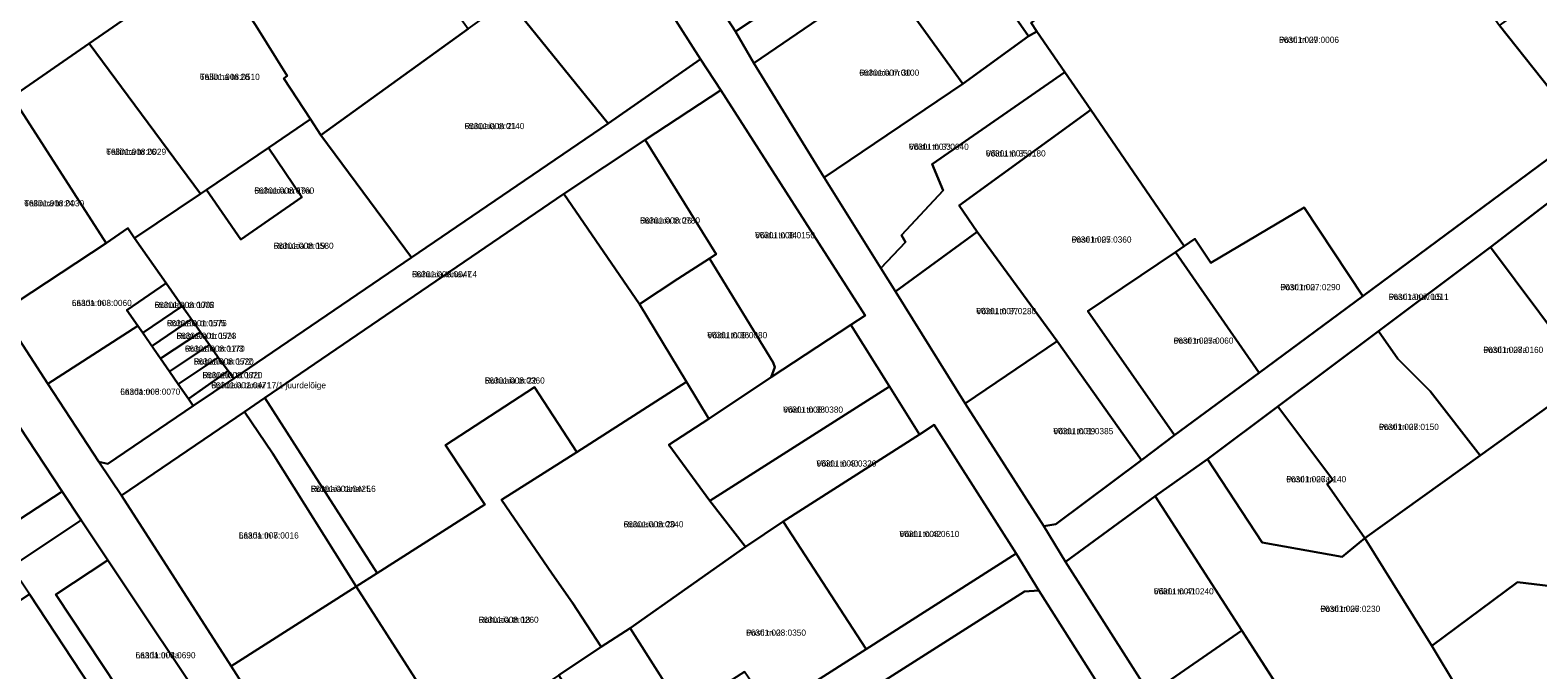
# Model space of a CAD drawing. Extents: x 632278 to 636344, y 6578401 to 6583362.
# Drawn here: x 634219.9 to 634584.8, y 6581569.1 to 6581724.1 of the extents above; entities that cross this region are included whole.
import ezdxf

# ---------------------------------------------------------------- set-up
doc = ezdxf.new("R2010")
doc.units = 0
for name, color, linetype in [('L_AADRESS', 7, 'Continuous'), ('PIIR', 7, 'Continuous'), ('TUNNUS', 7, 'Continuous')]:
    doc.layers.add(name, color=color, linetype=linetype)

msp = doc.modelspace()

# ---------------------------------------------------------------- linework, layer by layer
at = {"layer": 'PIIR'}
for points in [[(634390.59, 6581723.7), (634406.97, 6581734.67), (634430.14, 6581750.99), (634463.52, 6581774.56), (634480.53, 6581786.77), (634533.21, 6581825.04), (634540.52, 6581819.75), (634516.54, 6581802.4), (634487.79, 6581781.63), (634480.74, 6581776.54), (634463.1, 6581763.8), (634442.96, 6581749.29), (634426.52, 6581737.65), (634395.02, 6581716.06)], [(634542.38, 6581659.66), (634528.25, 6581681.09), (634505.64, 6581667.69), (634501.78, 6581673.52), (634499.19, 6581671.71), (634476.56, 6581704.76), (634470.29, 6581713.85), (634463.54, 6581723.76), (634462.17, 6581725.81), (634478.91, 6581739.1), (634495.28, 6581752.06), (634495.31, 6581755.28), (634480.74, 6581776.54), (634487.79, 6581781.63), (634501.69, 6581761.6), (634506.42, 6581760.84), (634533.2, 6581780.82), (634535.35, 6581782.3), (634539.41, 6581777.64), (634559.86, 6581753.58), (634578.17, 6581731.87), (634573.15, 6581728.47), (634575.51, 6581725.17), (634596.02, 6581699.37)], [(634384.46, 6581770.81), (634385.8, 6581770.55), (634390.5, 6581773.35), (634392.48, 6581770.44), (634390.31, 6581758.54), (634406.97, 6581734.67), (634390.59, 6581723.7), (634366.06, 6581761.71)], [(634287.77, 6581702.49), (634281.27, 6581712.39), (634282.11, 6581712.99), (634274.53, 6581725.21), (634263.89, 6581741.44), (634297.55, 6581763.99), (634325.89, 6581724.38), (634290.29, 6581698.63)], [(634463.54, 6581723.76), (634461.5, 6581722.59), (634442.96, 6581749.29), (634463.1, 6581763.8), (634478.91, 6581739.1), (634462.17, 6581725.81)], [(634332.09, 6581728.85), (634329.74, 6581732.36), (634338.88, 6581738.71), (634359, 6581752.83), (634371.92, 6581733.15), (634382.16, 6581717.03), (634359.75, 6581701.47), (634335.78, 6581731.17)], [(634426.52, 6581737.65), (634442.96, 6581749.29), (634461.5, 6581722.59), (634445.61, 6581711.1)], [(634575.51, 6581725.17), (634601.75, 6581744.08), (634619.36, 6581722.13), (634619.15, 6581716.25), (634596.02, 6581699.37)], [(634234.17, 6581720.87), (634263.89, 6581741.44), (634274.53, 6581725.21), (634282.11, 6581712.99), (634281.27, 6581712.39), (634287.77, 6581702.49), (634277.55, 6581695.55), (634262.59, 6581685.41), (634261.09, 6581684.41)], [(634395.02, 6581716.06), (634426.52, 6581737.65), (634445.61, 6581711.1), (634412.03, 6581688.4)], [(634290.29, 6581698.63), (634325.89, 6581724.38), (634332.09, 6581728.85), (634335.78, 6581731.17), (634359.75, 6581701.47), (634312.2, 6581669.01)], [(634412.03, 6581688.4), (634445.61, 6581711.1), (634461.5, 6581722.59), (634463.54, 6581723.76), (634470.29, 6581713.85), (634438.2, 6581691.62), (634440.85, 6581685.2), (634430.79, 6581674.37), (634431.73, 6581672.7), (634425.76, 6581666.4)], [(634465.25, 6581603.88), (634468.13, 6581604.4), (634488.84, 6581619.91), (634496.87, 6581625.93), (634517.35, 6581641.08), (634542.38, 6581659.66), (634596.02, 6581699.37), (634619.15, 6581716.25), (634619.36, 6581722.13), (634629.3, 6581709.96), (634624.28, 6581710.25), (634591.07, 6581685.14), (634573.32, 6581671.48), (634546.18, 6581651.15), (634521.83, 6581632.88), (634504.86, 6581620.14), (634492.15, 6581611.16), (634470.5, 6581595.28)], [(634234.17, 6581720.87), (634261.09, 6581684.41), (634245.18, 6581673.71), (634243.53, 6581676.07), (634238.31, 6581672.46), (634215.55, 6581707.95)], [(634238.7, 6581619.03), (634259.34, 6581633.1), (634269.19, 6581639.69), (634312.2, 6581669.01), (634359.75, 6581701.47), (634382.16, 6581717.03), (634387.02, 6581709.56), (634368.71, 6581697.52), (634349.07, 6581684.39), (634276.71, 6581634.98), (634271.75, 6581631.6), (634241.99, 6581611.37), (634236.5, 6581619.47)], [(634449.07, 6581675.23), (634429.3, 6581660.73), (634425.76, 6581666.4), (634431.73, 6581672.7), (634430.79, 6581674.37), (634440.85, 6581685.2), (634438.2, 6581691.62), (634470.29, 6581713.85), (634476.56, 6581704.76), (634444.69, 6581681.63)], [(634213, 6581655.75), (634200.62, 6581674.99), (634198.64, 6581684.01), (634200.14, 6581693.09), (634205.31, 6581700.81), (634215.55, 6581707.95), (634238.31, 6581672.46)], [(634385.92, 6581669.79), (634368.71, 6581697.52), (634387.02, 6581709.56), (634421.96, 6581654.97), (634418.54, 6581652.72), (634399.27, 6581640), (634400.16, 6581642.46), (634399.72, 6581643.55), (634384.33, 6581668.75)], [(634449.07, 6581675.23), (634444.69, 6581681.63), (634476.56, 6581704.76), (634499.19, 6581671.71), (634497.12, 6581670.26), (634475.86, 6581655.98), (634496.87, 6581625.93), (634488.84, 6581619.91), (634468.44, 6581648.74)], [(634277.55, 6581695.55), (634287.77, 6581702.49), (634290.29, 6581698.63), (634312.2, 6581669.01), (634269.19, 6581639.69), (634267.81, 6581641.52), (634265.41, 6581644.76), (634263.27, 6581647.84), (634261.09, 6581650.95), (634256.71, 6581657.23), (634252.82, 6581662.79), (634245.18, 6581673.71), (634261.09, 6581684.41), (634262.59, 6581685.41), (634270.9, 6581673.36), (634285.64, 6581683.59)], [(634262.59, 6581685.41), (634277.55, 6581695.55), (634285.64, 6581683.59), (634270.9, 6581673.36)], [(634368.71, 6581697.52), (634385.92, 6581669.79), (634384.33, 6581668.75), (634376.63, 6581663.86), (634367.4, 6581657.66), (634349.07, 6581684.39)], [(634591.07, 6581685.14), (634616.16, 6581653.62), (634596.98, 6581639.85), (634573.32, 6581671.48)], [(634178.6, 6581682.42), (634181.78, 6581682), (634227.65, 6581612.34), (634201.03, 6581594.97), (634184.81, 6581620.64), (634154.84, 6581666.74)], [(634329.95, 6581609.13), (634303.87, 6581592.51), (634276.71, 6581634.98), (634349.07, 6581684.39), (634367.4, 6581657.66), (634378.72, 6581638.87), (634352.19, 6581621.81), (634341.95, 6581637.56), (634320.42, 6581623.52)], [(634497.12, 6581670.26), (634499.19, 6581671.71), (634501.78, 6581673.52), (634505.64, 6581667.69), (634528.25, 6581681.09), (634542.38, 6581659.66), (634517.35, 6581641.08)], [(634213, 6581655.75), (634238.31, 6581672.46), (634243.53, 6581676.07), (634245.18, 6581673.71), (634252.82, 6581662.79), (634243.3, 6581656.27), (634245.94, 6581652.46), (634224.2, 6581638.41)], [(634429.3, 6581660.73), (634449.07, 6581675.23), (634468.44, 6581648.74), (634446.2, 6581633.64)], [(634517.35, 6581641.08), (634496.87, 6581625.93), (634475.86, 6581655.98), (634497.12, 6581670.26)], [(634558.68, 6581636.62), (634550.9, 6581644.45), (634546.18, 6581651.15), (634573.32, 6581671.48), (634596.98, 6581639.85), (634570.79, 6581621.02)], [(634376.63, 6581663.86), (634384.33, 6581668.75), (634399.72, 6581643.55), (634400.16, 6581642.46), (634399.27, 6581640), (634384.14, 6581629.88), (634378.72, 6581638.87), (634367.4, 6581657.66)], [(634243.3, 6581656.27), (634252.82, 6581662.79), (634256.71, 6581657.23), (634247.14, 6581650.73), (634245.94, 6581652.46)], [(634256.71, 6581657.23), (634258.93, 6581654.05), (634249.39, 6581647.48), (634247.14, 6581650.73)], [(634236.5, 6581619.47), (634224.2, 6581638.41), (634245.94, 6581652.46), (634247.14, 6581650.73), (634251.44, 6581644.52), (634253.6, 6581641.4), (634255.73, 6581638.31), (634258.19, 6581634.76), (634259.34, 6581633.1), (634238.7, 6581619.03)], [(634261.09, 6581650.95), (634251.44, 6581644.52), (634249.39, 6581647.48), (634258.93, 6581654.05)], [(634374.47, 6581623.59), (634384.14, 6581629.88), (634399.27, 6581640), (634418.54, 6581652.72), (634427.83, 6581637.77), (634384.4, 6581610.07)], [(634559.13, 6581574.95), (634542.92, 6581601.03), (634570.79, 6581621.02), (634596.98, 6581639.85), (634616.16, 6581653.62), (634622.65, 6581644.36), (634632.64, 6581630.11), (634606.62, 6581611.45), (634614.1, 6581600.53), (634608.38, 6581596.32), (634597.33, 6581588.27), (634579.85, 6581590.37)], [(634251.44, 6581644.52), (634261.09, 6581650.95), (634263.27, 6581647.84), (634253.6, 6581641.4)], [(634446.2, 6581633.64), (634468.44, 6581648.74), (634488.84, 6581619.91), (634468.13, 6581604.4), (634465.25, 6581603.88)], [(634533.76, 6581614.08), (634535.12, 6581615.13), (634521.83, 6581632.88), (634546.18, 6581651.15), (634550.9, 6581644.45), (634558.68, 6581636.62), (634570.79, 6581621.02), (634542.92, 6581601.03)], [(634253.6, 6581641.4), (634263.27, 6581647.84), (634265.41, 6581644.76), (634255.73, 6581638.31)], [(634255.73, 6581638.31), (634265.41, 6581644.76), (634267.81, 6581641.52), (634258.19, 6581634.76)], [(634269.19, 6581639.69), (634259.34, 6581633.1), (634258.19, 6581634.76), (634267.81, 6581641.52)], [(634298.81, 6581589.28), (634303.87, 6581592.51), (634329.95, 6581609.13), (634320.42, 6581623.52), (634341.95, 6581637.56), (634352.19, 6581621.81), (634333.97, 6581610.3), (634346.21, 6581592.35), (634351.19, 6581585.34), (634358.09, 6581574.66), (634347.82, 6581567.79), (634331.08, 6581556.63), (634331.92, 6581555.12), (634324.08, 6581549.93)], [(634358.09, 6581574.66), (634351.19, 6581585.34), (634346.21, 6581592.35), (634333.97, 6581610.3), (634352.19, 6581621.81), (634378.72, 6581638.87), (634384.14, 6581629.88), (634374.47, 6581623.59), (634384.4, 6581610.07), (634393.05, 6581598.93), (634365.1, 6581579.21)], [(634384.4, 6581610.07), (634427.83, 6581637.77), (634435.17, 6581626.1), (634402.11, 6581605.04), (634393.05, 6581598.93)], [(634276.71, 6581634.98), (634303.87, 6581592.51), (634298.81, 6581589.28), (634278.53, 6581621.61), (634271.75, 6581631.6)], [(634271.75, 6581631.6), (634278.53, 6581621.61), (634298.81, 6581589.28), (634268.56, 6581570.01), (634241.99, 6581611.37)], [(634537.45, 6581596.52), (634518.08, 6581599.98), (634504.86, 6581620.14), (634521.83, 6581632.88), (634535.12, 6581615.13), (634533.76, 6581614.08), (634542.92, 6581601.03)], [(634402.11, 6581605.04), (634435.17, 6581626.1), (634438.67, 6581628.47), (634458.52, 6581597.29), (634422.2, 6581574.09)], [(634526.88, 6581557.26), (634513.13, 6581578.68), (634492.15, 6581611.16), (634504.86, 6581620.14), (634518.08, 6581599.98), (634537.45, 6581596.52), (634542.92, 6581601.03), (634559.13, 6581574.95), (634565.3, 6581564.63), (634538.81, 6581546.18), (634536.83, 6581548.73), (634529.38, 6581553.31)], [(634122.7, 6581544.91), (634155.45, 6581566.31), (634155.98, 6581565.48), (634173.91, 6581577.27), (634196.07, 6581591.73), (634201.03, 6581594.97), (634227.65, 6581612.34), (634232.23, 6581605.4), (634215.35, 6581594.07), (634143.16, 6581546.1), (634126.02, 6581534.77)], [(634470.5, 6581595.28), (634492.15, 6581611.16), (634513.13, 6581578.68), (634490.9, 6581563.22)], [(634215.35, 6581594.07), (634232.23, 6581605.4), (634238.73, 6581595.7), (634226.13, 6581587.37), (634252.18, 6581547.97), (634258.61, 6581538.24), (634265.76, 6581527.41), (634283.88, 6581498.21), (634285.44, 6581499.17), (634288.97, 6581494.15), (634283.51, 6581490.57), (634253.15, 6581536.68), (634219.73, 6581587.47)], [(634385.83, 6581564.23), (634389.39, 6581559.07), (634392.04, 6581554.92), (634383.79, 6581549.73), (634365.1, 6581579.21), (634393.05, 6581598.93), (634402.11, 6581605.04), (634422.2, 6581574.09), (634398.79, 6581559.22), (634396.33, 6581563.46), (634392.79, 6581568.66)], [(634311.42, 6581503.24), (634349.58, 6581527.87), (634366.58, 6581538.6), (634383.79, 6581549.73), (634392.04, 6581554.92), (634398.79, 6581559.22), (634422.2, 6581574.09), (634458.52, 6581597.29), (634464.03, 6581588.35), (634460.52, 6581588.08), (634423.26, 6581564.33), (634392.45, 6581544.4), (634388.55, 6581541.72), (634370.84, 6581530.29), (634352.1, 6581517.99), (634334.35, 6581506.61), (634316.67, 6581495.15)], [(634238.73, 6581595.7), (634264.73, 6581556.64), (634252.18, 6581547.97), (634226.13, 6581587.37)], [(634538.81, 6581546.18), (634565.3, 6581564.63), (634559.13, 6581574.95), (634579.85, 6581590.37), (634597.33, 6581588.27), (634608.38, 6581596.32), (634629.28, 6581564.12), (634560.66, 6581514.66), (634555.66, 6581521.89)], [(634201.5, 6581550.59), (634190.04, 6581567.87), (634219.73, 6581587.47), (634253.15, 6581536.68), (634223.55, 6581517.33)], [(634298.81, 6581589.28), (634324.08, 6581549.93), (634312.46, 6581542.22), (634294.09, 6581530), (634268.56, 6581570.01)], [(634460.52, 6581588.08), (634464.03, 6581588.35), (634484.84, 6581555.48), (634445.34, 6581530.31), (634423.26, 6581564.33)], [(634347.82, 6581567.79), (634358.09, 6581574.66), (634365.1, 6581579.21), (634383.79, 6581549.73), (634366.58, 6581538.6)], [(634490.9, 6581563.22), (634513.13, 6581578.68), (634526.89, 6581557.28), (634504.23, 6581541.92)]]:
    msp.add_lwpolyline(points, close=True, dxfattribs=at)
for points in [[(634366.06, 6581761.71), (634390.59, 6581723.7), (634395.02, 6581716.06), (634412.03, 6581688.4), (634425.76, 6581666.4), (634429.3, 6581660.73), (634446.2, 6581633.64), (634465.25, 6581603.88), (634470.5, 6581595.28), (634490.9, 6581563.22), (634504.23, 6581541.92), (634512.73, 6581527.76), (634519.26, 6581517.48), (634520.6, 6581515.15), (634532.79, 6581495.33), (634537.33, 6581488.04), (634558.25, 6581454.99), (634577.69, 6581424.67), (634621.73, 6581353.95), (634627.88, 6581343.38), (634643.98, 6581315.73), (634660.16, 6581290.01), (634668.51, 6581276.9), (634697.09, 6581244.95)], [(634263.89, 6581741.44), (634234.17, 6581720.87), (634215.55, 6581707.95)], [(634587.89, 6581389.49), (634576.29, 6581408.42), (634557.03, 6581439.92), (634529.98, 6581483.12), (634525.77, 6581490.04), (634514.12, 6581508.57), (634505.52, 6581522.13), (634493.97, 6581541.09), (634484.84, 6581555.48), (634464.03, 6581588.35), (634458.52, 6581597.29), (634438.67, 6581628.47), (634435.17, 6581626.1), (634427.83, 6581637.77), (634418.54, 6581652.72), (634421.96, 6581654.97), (634387.02, 6581709.56), (634382.16, 6581717.03), (634371.92, 6581733.15)], [(634264.73, 6581556.64), (634238.73, 6581595.7), (634232.23, 6581605.4), (634227.65, 6581612.34), (634181.78, 6581682)], [(634213, 6581655.75), (634224.2, 6581638.41), (634236.5, 6581619.47), (634241.99, 6581611.37), (634268.56, 6581570.01), (634294.09, 6581530)]]:
    msp.add_lwpolyline(points, dxfattribs=at)

# ---------------------------------------------------------------- texts
at = {"layer": 'L_AADRESS'}
for s, p in [('Posti tn 29', (634522.14, 6581720.98)), ('Rohuaia tn 30', (634420.56, 6581713.02)), ('Tallinna tn 28', (634260.97, 6581712)), ('Rohuaia tn 21', (634325.02, 6581700.09)), ('Tallinna tn 26', (634238.32, 6581693.86)), ('Võidu tn 33', (634432.55, 6581695.08)), ('Võidu tn 35', (634451.16, 6581693.46)), ('Rohuaia tn 19a', (634274.15, 6581684.46)), ('Tallinna tn 24', (634218.48, 6581681.38)), ('Rohuaia tn 26', (634367.5, 6581677.22)), ('Võidu tn 34', (634395.34, 6581673.65)), ('Posti tn 25', (634471.94, 6581672.6)), ('Rohuaia tn 19', (634278.84, 6581671.09)), ('Rohuaia tänav L4', (634312.32, 6581664.2)), ('Posti tn 27', (634522.46, 6581661.08)), ('Posti tänav L5', (634548.68, 6581658.71)), ('Laada tn 3', (634229.99, 6581657.24)), ('Rohuaia tn 17/6', (634250.02, 6581656.76)), ('Võidu tn 37', (634448.87, 6581655.27)), ('Rohuaia tn 17/5', (634253, 6581652.36)), ('Rohuaia tn 17/4', (634255.3, 6581649.29)), ('Võidu tn 36', (634383.78, 6581649.44)), ('Posti tn 25a', (634496.61, 6581648.11)), ('Rohuaia tn 17/3', (634257.35, 6581646.17)), ('Rohuaia tn 17/2', (634259.5, 6581643.07)), ('Posti tn 28a', (634571.58, 6581645.88)), ('Rohuaia tn 17/1', (634261.61, 6581639.76)), ('Laada tn 5', (634241.72, 6581635.75)), ('Rohuaia tänav 17/1 juurdelõige', (634263.73, 6581637.31)), ('Rohuaia tn 22', (634329.93, 6581638.45)), ('Võidu tn 38', (634402.12, 6581631.4)), ('Võidu tn 39', (634467.52, 6581626.2)), ('Posti tn 28', (634546.31, 6581627.21)), ('Võidu tn 40', (634410.19, 6581618.35)), ('Posti tn 26a', (634523.89, 6581614.54)), ('Rohuaia tänav L6', (634287.81, 6581612.22)), ('Rohuaia tn 20', (634363.51, 6581603.63)), ('Laada tn 7', (634270.4, 6581600.93)), ('Võidu tn 42', (634430.27, 6581601.28)), ('Võidu tn 41', (634491.82, 6581587.39)), ('Posti tn 26', (634532.13, 6581583.16)), ('Rohuaia tn 18', (634328.45, 6581580.5)), ('Posti tn 23', (634393.16, 6581577.38)), ('Laada tn 4a', (634245.43, 6581571.91))]:
    msp.add_text(s, height=1.5, dxfattribs=at).set_placement(p)
at = {"layer": 'TUNNUS'}
for s, p in [('66301:007:0006', (634522.14, 6581720.98)), ('66301:007:0100', (634420.56, 6581713.02)), ('66301:008:0510', (634260.97, 6581712)), ('66301:008:0140', (634325.02, 6581700.09)), ('66301:008:0029', (634238.32, 6581693.86)), ('66301:007:0040', (634432.55, 6581695.08)), ('66301:007:0180', (634451.16, 6581693.46)), ('66301:008:0760', (634274.15, 6581684.46)), ('66301:008:0030', (634218.48, 6581681.38)), ('66301:008:0780', (634367.5, 6581677.22)), ('66301:008:0150', (634395.34, 6581673.65)), ('66301:007:0360', (634471.94, 6581672.6)), ('66301:008:0580', (634278.84, 6581671.09)), ('66301:008:0047', (634312.32, 6581664.2)), ('66301:007:0290', (634522.46, 6581661.08)), ('66301:007:0011', (634548.68, 6581658.71)), ('66301:008:0060', (634229.99, 6581657.24)), ('66301:008:0008', (634250.02, 6581656.76)), ('66301:007:0280', (634448.87, 6581655.27)), ('66301:001:0576', (634253, 6581652.36)), ('66301:001:0523', (634255.3, 6581649.29)), ('66301:008:0080', (634383.78, 6581649.44)), ('66301:007:0060', (634496.61, 6581648.11)), ('66301:008:0170', (634257.35, 6581646.17)), ('66301:008:0520', (634259.5, 6581643.07)), ('66301:007:0160', (634571.58, 6581645.88)), ('66301:008:0820', (634261.61, 6581639.76)), ('66301:008:0070', (634241.72, 6581635.75)), ('66301:001:0471', (634263.73, 6581637.31)), ('66301:008:0360', (634329.93, 6581638.45)), ('66301:008:0380', (634402.12, 6581631.4)), ('66301:001:0385', (634467.52, 6581626.2)), ('66301:007:0150', (634546.31, 6581627.21)), ('66301:008:0320', (634410.19, 6581618.35)), ('66301:007:0140', (634523.89, 6581614.54)), ('66301:001:0425', (634287.81, 6581612.22)), ('66301:008:0340', (634363.51, 6581603.63)), ('66301:008:0016', (634270.4, 6581600.93)), ('66301:008:0610', (634430.27, 6581601.28)), ('66301:007:0240', (634491.82, 6581587.39)), ('66301:007:0230', (634532.13, 6581583.16)), ('66301:008:0260', (634328.45, 6581580.5)), ('66301:008:0350', (634393.16, 6581577.38)), ('66301:008:0690', (634245.43, 6581571.91))]:
    msp.add_text(s, height=1.5, dxfattribs=at).set_placement(p)

doc.saveas('drawing.dxf')
